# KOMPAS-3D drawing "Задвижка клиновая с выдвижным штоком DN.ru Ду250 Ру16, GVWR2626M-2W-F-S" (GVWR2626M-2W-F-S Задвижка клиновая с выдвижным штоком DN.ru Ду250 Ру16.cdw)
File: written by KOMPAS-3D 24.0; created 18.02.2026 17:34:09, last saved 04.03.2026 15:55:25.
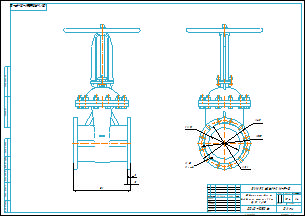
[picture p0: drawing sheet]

Document properties: Автор: R2D2; Форматы листов документа: A2; Полное имя файла: GVWR2626M-2W-F-S Задвижка клиновая с выдвижным штоком DN.ru Ду250 Ру16.m3d; Масса: 154; Наименование: Задвижка клиновая с выдвижным штоком DN.ru Ду250 Ру16; Количество листов документа: 1; Примечание: D040-10506

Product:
- Part/product: Задвижка клиновая с выдвижным штоком DN.ru Ду250 Ру16  | designation GVWR2626M-2W-F-S
    Масса: 154
    Раздел спецификации: Прочие изделия
    Примечание: D040-10506

Referenced files in E:\Работа\Зайцев\Для компаса\: чертеж DN.ru А3.cdt
Referenced files in E:\Работа\Зайцев\GVWR2626M-2W-F-S Задвижка клиновая с выдвижным штоком DN.ru Ду50-300 Ру16\DN250\: GVWR2626M-2W-F-S Задвижка клиновая с выдвижным штоком DN.ru Ду250 Ру16.m3d
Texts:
  чертеж DN.ru А3.cdt
  Задвижка клиновая с
  выдвижным штоком DN.ru
  Ду250 Ру16
  GVWR2626M-2W-F-S
  Задвижка клиновая с выдвижным штоком DN.ru Ду250 Ру16
  GVWR2626M-2W-F-S Задвижка клиновая с выдвижным штоком DN.ru Ду250 Ру16
Dimensions and other numbers on the sheet: 1:4; 0; 1; 2; 154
